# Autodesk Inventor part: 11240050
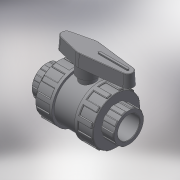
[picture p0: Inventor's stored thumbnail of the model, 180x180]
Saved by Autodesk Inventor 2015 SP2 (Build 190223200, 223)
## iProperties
Created: 2017-11
Part Number: 11240050
Material: Generic
Description: PLASSON BI STOP VALVE CEM PVC 50
Document SubType Name: Modeling
Designer: KIM
Density: 1 g/cm^3
Appearance: Default
Author: KIM
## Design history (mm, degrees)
derived "112400 - 112700.ipt"
feature "Solid1::112400 - 112700.ipt"
tag "TaggingFeature1"
body "Solid1"
other parameters: "d0" = 142, "d2" = 96, "d3" = 31, "d5" = 21.7, "d8" = 86.4, "d13" = 1.5, "d23" = 31, "d24" = 92.16, "d25" = 1, "d26" = 1.5, "d27" = 14.4, "d28" = 7.2, "d29" = 23.25, "d30" = 0, "d35" = 1.5, "d39" = 48, "d45" = 360 deg, "d47" = 1, "d50" = 52.8, "d51" = 28.8, "d53" = 0, "d56" = 5, "d57" = 21.7, "d58" = 0, "d59" = 1.5, "d61" = 360 deg, "d63" = 38.4, "d64" = 86, "d68" = 19.2, "d69" = 33, "d70" = 21.5, "d71" = 3 deg, "d73" = 1.92, "d74" = 44, "d75" = 2.58, "d76" = 0, "d77" = 1, "l_" = 31, "H_" = 142, "K_" = 96, "F_" = 86, "d67" = 38.4, "d72" = 9.6
